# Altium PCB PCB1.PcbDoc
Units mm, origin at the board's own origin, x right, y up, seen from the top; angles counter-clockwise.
Board outline 24 x 24.06 mm, 2 copper layers (Top Layer, Bottom Layer); 36 components, 33 nets, 153 pads, 41 vias.
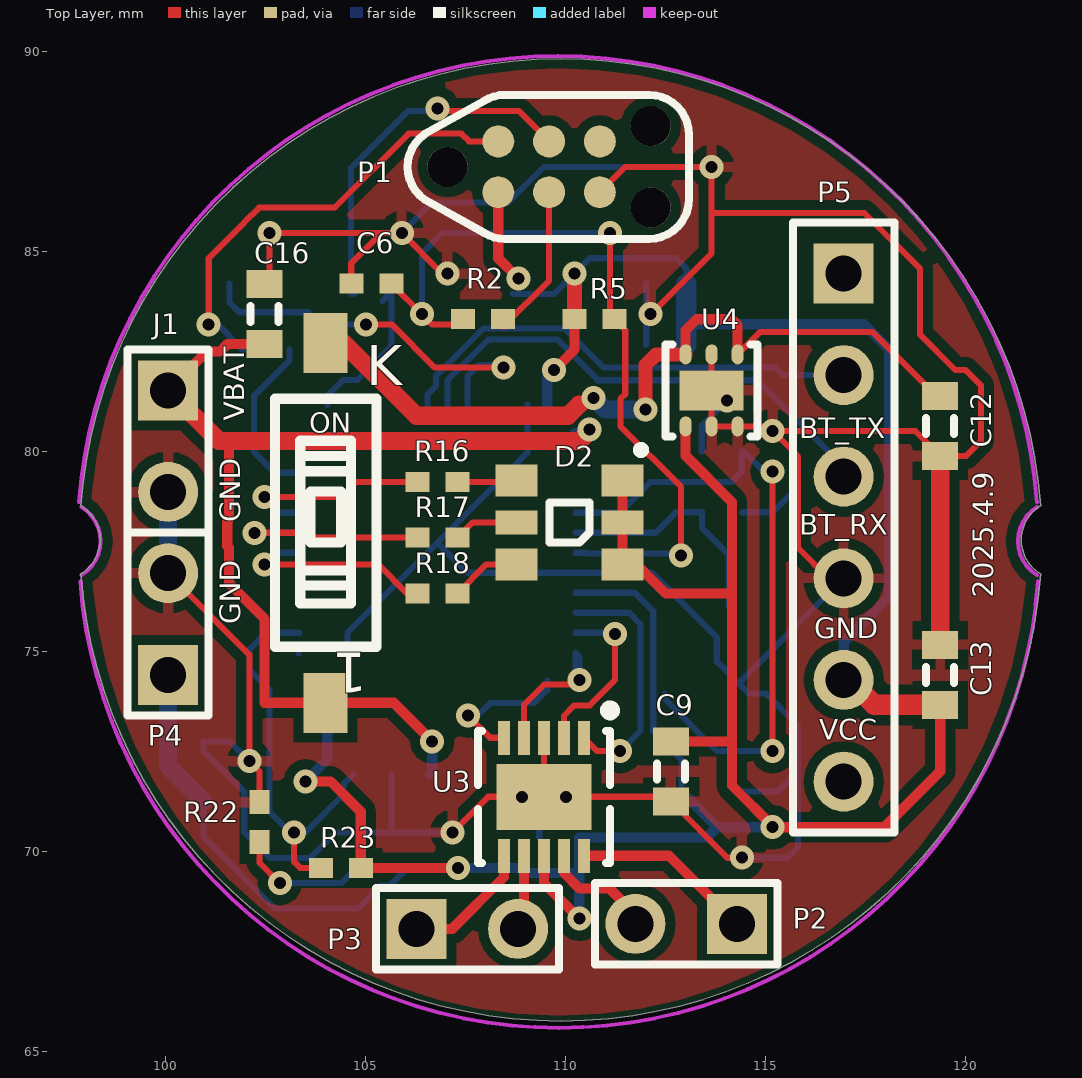
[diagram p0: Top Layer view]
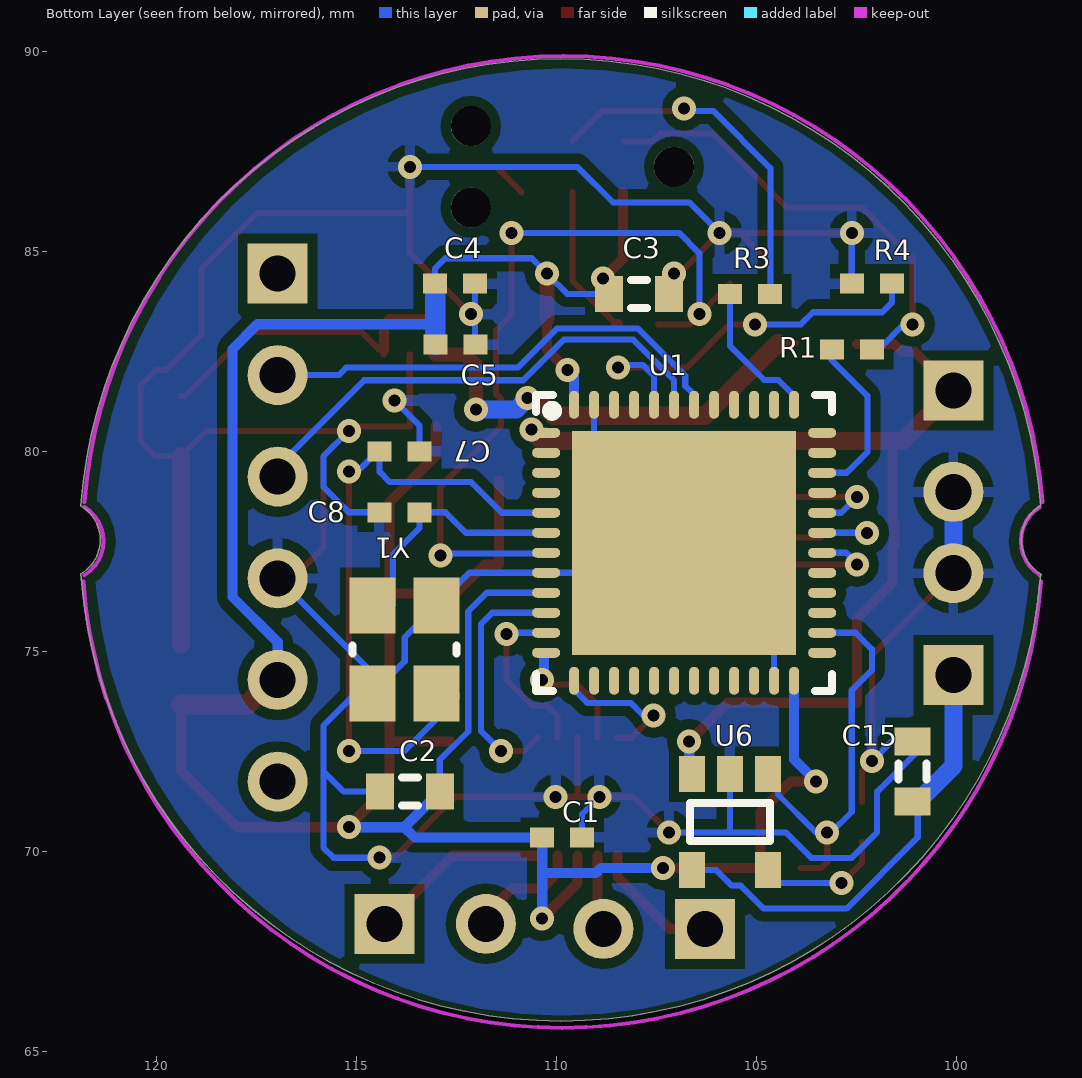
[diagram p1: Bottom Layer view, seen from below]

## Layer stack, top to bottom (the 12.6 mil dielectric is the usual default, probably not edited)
Top Solder: solder mask 0.0102, Solder Resist, Dk 3.5
Top Layer: signal copper 0.0356
Dielectric 1: dielectric 0.32, FR-4, Dk 4.8
Bottom Layer: signal copper 0.0356
Bottom Solder: solder mask 0.0102, Solder Resist, Dk 3.5

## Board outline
97.893,76.946 ccw(c97.392,77.796) 97.894,78.646 cw(c109.892,77.796) 121.89,78.648 121.891,78.646 ccw(c122.392,77.796) 121.89,76.946 cw(c109.892,77.796)

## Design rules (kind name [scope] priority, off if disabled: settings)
Clearance [All] p1: gap=0.254 except(0.127: Arc-Arc Track-SMDPad Arc-Track Arc-SMDPad Track-Track SMDPad-SMDPad)
PolygonConnect [All] p1: connectstyle=Relief reliefconductorwidth=0.254 reliefentries=4 polygonreliefangle="90 Angle" airgapwidth=0.254
RoutingVias [All] p1: holewidth=0.711 width=1.27 viastyle="Through Hole" minholewidth=0.711 minwidth=1.27 maxholewidth=0.711 maxwidth=1.27
SolderMaskExpansion [All] p1: expansion=0.102
UnpouredPolygon [All] p1: allowunpoured=FALSE
Width [All] p1: maxlimit=0.254 minlimit=0.127 preferedwidth=0.152 minimp=50.000000 maximp=50.000000 favimp=50.000000
29 further rules are at their usual default settings.

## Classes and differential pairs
net class MOTOR_CONTROL[1..4]: MOTOR_CONTROL1 MOTOR_CONTROL2 MOTOR_CONTROL3 MOTOR_CONTROL4
net class RGBLED[1..3]: RGBLED1 RGBLED2 RGBLED3

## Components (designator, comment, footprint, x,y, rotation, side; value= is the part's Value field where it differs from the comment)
C1 "10nF" 0402 109.855,70.358 r0 bottom
C2 "1uF" 0603 113.665,71.502 r180 bottom
C3 "4.7uF" 0603 107.938,83.947 r0 bottom
C4 "100nF" 0402 112.53,84.201 r0 bottom
C5 "100nF" 0402 112.522,82.677 r0 bottom
C6 "100nF" 0402 105.156,84.201 r0 top
C7 "22pF" 0402 113.919,80.01 r0 bottom
C8 "22pF" 0402 113.927,78.486 r180 bottom
C9 "10uF" 0603 112.649,72.009 r90 top
C12 "1uF" 0603 119.38,80.645 r90 top
C13 "1uF" 0603 119.38,74.422 r270 top
C15 "4.7uF" 0603 101.092,72.009 r270 bottom
C16 "4.7uF" 0603 102.489,83.439 r270 top
D2 "SMLVN6RGB1W1" "3.5x2.8 mm 6-SMD" 110.109,78.232 r180 top
J1 "78171-0002" HDR1*2 100.076,80.264 r0 top
K "2.54-1P-PGT" SW-SMD_2P-L6.2-LS9.4 104.013,78.359 r90 top
P1 "TC2030-IDC-NL" TC2030-IDC-NL 109.601,87.122 r0 top
P2 "HEADER 2X1 0.05\" UNPOLARIZED" HDR1*2 113.03,68.199 r270 top
P3 "HEADER 2X1 0.05\" UNPOLARIZED" HDR1*2 107.557,68.072 r90 top
P4 "CHARGING PAD" HDR1*2 100.076,75.692 r180 top
P5 "Header 6" HDR1X6 116.967,84.455 r270 top
R1 "22R" 0402 102.616,82.55 r180 bottom
R2 "22R" 0402 107.95,83.312 r0 top
R3 "22R" 0402 105.164,83.947 r180 bottom
R4 "100K" 0402 102.108,84.201 r180 bottom
R5 "100K" 0402 110.736,83.312 r180 top
R16 "22.6R" 0402 106.807,79.248 r0 top
R17 "130R" 0402 106.807,77.851 r0 top
R18 "24.9R" 0402 106.807,76.454 r0 top
R22 "10K" 0402 102.362,70.739 r90 top
R23 "100K" 0402 104.394,69.596 r0 top
U1 "STM32F051C8U6" QFN50P700X700X60_HS-49L 106.807,77.724 r180 bottom
U3 "A3901SEJTR-T" DFN50P300X300X75_HS-11N 109.474,71.374 r180 top
U4 "ADP122ACPZ-3.3-R7" "LFCSP-6 2.0X2.0X0.55" 113.665,81.534 r0 top
U6 "MCP73831T-2ACI/OT" SOT-23-OT5_L 105.664,70.739 r270 bottom
Y1 "7V-16.000MAAE-T" "3.2x2.5 CRYSTAL" 113.792,75.057 r90 bottom

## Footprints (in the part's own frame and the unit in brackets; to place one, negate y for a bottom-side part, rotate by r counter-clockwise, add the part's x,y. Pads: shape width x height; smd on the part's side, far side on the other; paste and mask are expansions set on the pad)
"3.2x2.5 CRYSTAL" [mm]
  rect 1.4x1.15 smd: 1(-1.1,-0.8) 2(1.1,-0.8) 3(1.1,0.8) 4(-1.1,0.8)
  silkscreen extent -0.1,-1.3 0.1,1.3, body extent -1.6,-1.25 1.6,1.25, height 0.8
"3.5x2.8 mm 6-SMD" [mm] "3.5 x 2.8 mm 6-SMD Flat Leads"
  rect 1.05x0.8 smd: 1(-1.325,1.05) 3(-1.325,-1.05) 4(1.325,-1.05) 6(1.325,1.05)
  rect 1.05x0.6 smd: 2(-1.325,0) 5(1.325,0)
  silkscreen extent -0.5,-0.5 0.5,0.5, body extent -1.75,-1.4 1.75,1.4, height 0.6
0402 [mm] "Chip Body 1.0 x 0.5 mm (LxW typ)"
  rect 0.6x0.5 smd: 1(-0.5,0) 2(0.5,0)
  body extent -0.55,-0.3 0.55,0.3, height 0.55
0603 [mm] "Chip Body 1.6 x 0.8 mm (LxW typ)"
  rect 0.7x0.9 smd: 1(-0.75,0) 2(0.75,0)
  silkscreen extent -0.2,-0.35 0.2,0.35, body extent -0.85,-0.48 0.85,0.48, height 0.9
DFN50P300X300X75_HS-11N [mm]
  rect 0.3x0.85 smd: 1(-1,-1.475) 2(-0.5,-1.475) 3(0,-1.475) 4(0.5,-1.475) 5(1,-1.475) 6(1,1.475) 7(0.5,1.475) 8(0,1.475) 9(-0.5,1.475) 10(-1,1.475)
  rect 2.38x1.65 smd: 11(0,0)
  silkscreen extent -1.78,-2.28 1.65,1.65, body extent -1.5,-1.5 1.5,1.5, height 0.75
HDR1*2 [mm]
  rect 1.5x1.5 hole 0.9: 1(0,1.27)
  round 1.5 hole 0.9: 2(0,-1.27)
  silkscreen extent -1.02,-2.29 1.02,2.29
HDR1X6 [mm] "Connector; Header; 6 Position"
  rect 1.5x1.5 hole 0.9: 1(0,0)
  round 1.5 hole 0.9: 2(2.54,0) 3(5.08,0) 4(7.62,0) 5(10.16,0) 6(12.7,0)
  silkscreen extent -1.27,-1.27 13.97,1.27
"LFCSP-6 2.0X2.0X0.55" [mm] ". 6-Lead Lead Frame Chip Scale Package [LFCSP_UD]  2.00 mm?2.00 mm Body, Ultra Thin, Dual Lead  (CP-6-3)"
  oval 0.3x0.5 smd: 1(-0.65,-0.9) 2(0,-0.9) 3(0.65,-0.9) 4(0.65,0.9) 5(0,0.9) 6(-0.65,0.9)
  rect 1.6x1 smd: 7(0,0)
  silkscreen extent -1.86,-1.59 1.15,1.15, body extent -1,-1 1,1, height 0.6
QFN50P700X700X60_HS-49L [mm] "QFN, 48-Leads, Body 7,00x7,00mm, Pitch 0,50mm, Thermal Pad 5,60x5,60mm, IPC High Density"
  oval 0.7x0.25 smd: 1(-3.45,2.75) 2(-3.45,2.25) 3(-3.45,1.75) 4(-3.45,1.25) 5(-3.45,0.75) 6(-3.45,0.25) 7(-3.45,-0.25) 8(-3.45,-0.75) 9(-3.45,-1.25) 10(-3.45,-1.75) 11(-3.45,-2.25) 12(-3.45,-2.75) 25(3.45,-2.75) 26(3.45,-2.25) 27(3.45,-1.75) 28(3.45,-1.25) 29(3.45,-0.75) 30(3.45,-0.25) 31(3.45,0.25) 32(3.45,0.75) 33(3.45,1.25) 34(3.45,1.75) 35(3.45,2.25) 36(3.45,2.75)
  oval 0.25x0.7 smd: 13(-2.75,-3.45) 14(-2.25,-3.45) 15(-1.75,-3.45) 16(-1.25,-3.45) 17(-0.75,-3.45) 18(-0.25,-3.45) 19(0.25,-3.45) 20(0.75,-3.45) 21(1.25,-3.45) 22(1.75,-3.45) 23(2.25,-3.45) 24(2.75,-3.45) 37(2.75,3.45) 38(2.25,3.45) 39(1.75,3.45) 40(1.25,3.45) 41(0.75,3.45) 42(0.25,3.45) 43(-0.25,3.45) 44(-0.75,3.45) 45(-1.25,3.45) 46(-1.75,3.45) 47(-2.25,3.45) 48(-2.75,3.45)
  rect 5.6x5.6 smd: 49(0,0)
  silkscreen extent -3.7,-3.7 3.7,3.7, body extent -3.55,-3.55 3.55,3.55, height 0.6
SOT-23-OT5_L [mm] "SOT23, 5-Leads, Body 2.9x1.6mm, Pitch 0.95mm, Lead Span 2.7mm, IPC High Density"
  rect 0.9x0.65 smd: 1(-1.2,0.95) 2(-1.2,0) 3(-1.2,-0.95) 4(1.2,-0.95) 5(1.2,0.95)
  silkscreen extent -0.48,-1 0.48,1, body extent -0.9,-1.55 0.9,1.55, height 1.45
SW-SMD_2P-L6.2-LS9.4 [mm]
  rect 1.5x1.1 smd paste+0 mask+0.051: 1(-4.636,-0.002) 2(4.364,-0.002)
  silkscreen extent -3.24,-1.27 2.96,1.27
TC2030-IDC-NL [mm] "TagConnector TC2030-IDC-NL"
  round 0.8 smd paste-1: 1(-1.27,-0.635) 2(-1.27,0.635) 3(0,-0.635) 4(0,0.635) 5(1.27,-0.635) 6(1.27,0.635)
  round 1 hole 1 unplated mask+0: ""(-2.54,0) ""(2.54,-1.016) ""(2.54,1.016)
  Top Layer pour cut-out: -1.27,-0.085 -1.27,0.085 -1.06,0.127 -0.881,0.246 -0.762,0.425 -0.72,0.635 -0.72,0.635 -0.55,0.635 -0.496,0.396 -0.343,0.205 -0.122,0.099 0.122,0.099 0.343,0.205 0.496,0.396 0.55,0.635 0.55,0.635 0.72,0.635 0.762,0.425 0.881,0.246 1.06,0.127 1.27,0.085 1.27,0.085 1.27,-0.085 1.06,-0.127 0.881,-0.246 0.762,-0.425 0.72,-0.635 0.72,-0.635 0.55,-0.635 0.496,-0.396 0.343,-0.205 0.122,-0.099 -0.122,-0.099 -0.343,-0.205 -0.496,-0.396 -0.55,-0.635 -0.55,-0.635 -0.72,-0.635 -0.762,-0.425 -0.881,-0.246 -1.06,-0.127 -1.27,-0.085
  silkscreen extent -3.54,-1.8 3.5,1.8, body extent -1.67,-1.03 1.67,1.03, height 0

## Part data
C1: "10nF 0402 X7R 25V ±5%"
C2 C12 C13: "1uF 0603 X5R 10V ±10%"
C3 C15 C16: "4.7uF 0603 X5R 10V ±10%"
C4 C5 C6: "100nF 0402 X7R 16V ±10%"
C7 C8: "22pF 0402 NP0/CG0 50V ±5%"
C9: "10uF 0603 X5R 6.3V ±20%"
D2: "ROHM SMLVN6RGB1W1 LED Tri-Color Blue/Green/Red Chip LED 6-Pin 1411 T/RLED Tri-Color Blue/Green/Red Chip LED 6-Pin 1411"
J1: "Molex Pico-EZmate? Wire-to-Board Header, 2 contacts"
P1: "TagConnect TC2030-IDC-NL SWD Programming Connector"
P5: "Header, 6-Pin"
R1 R2 R3: "22R 0402 1/16W ±1%"
R4 R5 R23: "100K 0402 1/16W ±1%"
R16: "22.6R 0402 1/16W ±0.05R"
R17: "130R 0402 1/16W ±0.05R"
R18: "24.9R 0402 1/16W ±0.05R"
R22: "10K 0402 1/16W ±1%"
U1: "STMICROELECTRONICS  STM32F051C8U6  MCU 32BIT CORTEX-M0 48MHZ UFQFPN-48"
U3: "ALLEGRO MICROSYSTEMS - A3901SEJTR-T - IC, MOTOR DRIVER"
U4: "Analog Devices ADP122ACPZ-3.3-R7 - 5.5 V Input, 300 mA, Low Quiescent  Current, CMOS Linear Regulator"
U6: "Miniature Single-Cell, Fully Integrated Li-Ion, Li-Polymer Charge Management Controller, 4.2V, 5-Pin SOT-23, Industrial Temperature, Tape and Reel"
Y1: "TXC - 7V-16.000MAAE-T, 16MHZ, 30PPM, 12PF - CRYSTAL"

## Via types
v1: diameter 0.6, hole 0.3, Top Layer to Bottom Layer, 41 vias

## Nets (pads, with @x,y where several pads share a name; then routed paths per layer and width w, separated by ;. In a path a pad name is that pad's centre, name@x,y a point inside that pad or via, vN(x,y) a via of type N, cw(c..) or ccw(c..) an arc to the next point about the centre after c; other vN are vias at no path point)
+3.3V: C1.2 C2.2 C3.2 C4.2 C5.2 C9.2 C13.2 D2.1 D2.2 D2.3 P1.1 P5.5 R5.2 R23.2 U1.9 U1.24 U1.48 U3.8 U4.1 | length 81.6
  Top Layer w0.152: P5.5 P5.5@117.105,74.295
  Top Layer w0.254: v1(103.513,71.756) 104.139,71.756 104.894,71.001 R23.2 v1(107.33,69.597) ; P1.1 108.331,84.836 v1(108.838,84.329) ; U3.8 109.474,69.215 v1(110.363,68.326) ; v1(109.727,82.043) 110.236,82.552 R5.2 ; D2.3 D2.2 D2.1 111.794,77.182 112.522,76.454 114.173,76.454 ; C9.2 114.161,72.759 114.173,72.771 ; U4.1 113.015,79.898 114.173,78.74 114.173,76.454 ; v1(115.188,70.613) v1@115.214,70.613 ; C13.2 119.38,72.009 117.984,70.613 v1@115.214,70.613 ; 114.173,72.771 114.173,76.454 ; 114.173,72.771 114.173,71.654 v1@115.214,70.613
  Top Layer w0.381: R5.2 v1(110.236,84.455)
  Top Layer w0.508: P5.5@117.105,74.295 117.728,73.672 C13.2
  Bottom Layer w0.152: C3.2 109.728,83.947 v1(110.236,84.455) 110.617,84.836 112.776,84.836 113.03,84.582 C4.2 ; U1.9 111.74,76.474 112.205,76.009 112.205,73.006 112.915,72.295 C2.2@112.915,71.601
  Bottom Layer w0.254: v1@103.505,71.755 104.057,72.307 U1.24 ; v1(107.33,69.597) 108.802,69.597 108.803,69.596 108.883,69.596 109.007,69.472 110.355,69.472 ; U1.48 109.557,81.871 v1@109.601,81.915 ; v1@110.355,68.334 110.355,69.472 ; C2.2 113.803,70.613 ; 113.03,83.185 117.475,83.185 118.098,82.562 118.098,76.367 116.967,75.236 P5.5 ; v1(115.188,70.613) 113.803,70.613 ; 110.355,69.472 C1.2 113.548,70.358 113.803,70.613
  Bottom Layer w0.508: C5.2@113.03,82.677 113.03,83.185 C4.2
BT_RX: P5.3 U1.43 | length 12.5
  Bottom Layer w0.152: U1.43 107.057,81.784 108.077,82.804 109.813,82.804 110.829,81.788 114.808,81.788 116.967,79.629 P5.3
BT_TX: P5.2 U1.42 | length 12
  Bottom Layer w0.152: U1.42 106.557,81.425 106.778,81.646 106.778,81.9 107.961,83.083 109.982,83.083 110.964,82.102 115.256,82.102 115.443,81.915 P5.2
CHARGING: R23.1 U1.26 U6.1 | length 10.2
  Top Layer w0.152: v1(103.229,70.486) 103.229,69.747 103.38,69.596 R23.1
  Bottom Layer w0.152: U1.26 102.523,75.474 102.113,75.064 102.113,74.542 102.482,74.173 102.484,74.173 102.616,74.041 102.616,70.993 103.124,70.485 103.514,70.485 104.46,71.431 104.46,71.685 U6.1
GND: C1.1 C2.1 C3.1 C4.1 C5.1 C6.1 C7.1 C8.1 C9.1 C12.1 C13.1 C15.1 C16.1 J1.2 P1.5 P4.2 P5.4 R4.1 R22.2 U1.8 U1.23 U1.47 U1.49 U3.3 U3.11 U4.2 U4.3 U4.5 U4.7 U6.2 Y1.2 Y1.4 | length 121.3
  Top Layer w0.152: P4.2@100.076,76.581 100.457,76.581 102.108,74.93 v1(102.108,72.263) 102.362,72.009 R22.2 ; C16.1 102.616,84.316 v1(102.616,85.471) 105.418,85.471 ; C6.1 104.656,84.709 105.418,85.471 ; v1(107.061,84.455) 106.934,84.455 v1(105.918,85.471) 105.418,85.471 ; v1(107.188,70.485) 108.077,71.374 v1(108.924,71.374) U3.11 ; U3.3 U3.11 ; P1.5 111.506,87.122 v1(113.665,87.122) 113.665,85.979 ; v1(112.141,83.439) 113.665,84.963 113.665,85.979 ; U4.5 U4.7 U4.2 U4.3 115.073,80.634 v1(115.189,80.518) ; v1(114.419,69.85) 114.058,69.85 C9.1 112.534,71.374 v1(110.024,71.374) U3.11 ; P5.4 116.586,76.835 115.824,77.597 115.824,79.883 v1(115.189,80.518) ; 113.665,85.979 113.677,85.967 117.487,85.967 118.872,84.582 118.872,82.932 119.762,82.042 120.015,82.042 120.396,81.661 120.396,80.264 120.027,79.895 C12.1 118.757,80.518 v1(115.189,80.518)
  Top Layer w0.452: C13.1 C12.1
  Bottom Layer w0.152: C15.1@100.965,72.759 100.965,72.517 101.981,71.501 101.981,70.485 102.62,69.846 103.628,69.846 104.267,70.485 105.728,70.485 ; C15.1 101.612,72.759 v1(102.108,72.263) ; R4.1@102.616,84.209 v1(102.616,85.471) ; U1.23 104.557,75.474 U1.49 ; U6.2 105.664,70.549 105.728,70.485 ; v1(105.918,85.471) 106.68,86.233 108.585,86.233 109.474,87.122 v1(113.665,87.122) ; v1(107.188,70.485) 105.728,70.485 ; v1(108.924,71.374) 109.355,70.943 C1.1 ; U1.47 109.057,79.974 U1.49 ; C5.1@112.03,82.677 C4.1 ; C7.1 113.419,80.653 v1(114.046,81.28) ; C2.1 115.316,71.501 115.824,72.009 ; v1(114.419,69.85) 115.57,69.85 115.824,70.104 115.824,72.009 ; C8.1 115.189,78.486 115.824,79.121 115.824,79.883 v1(115.189,80.518) ; P5.4 116.962,76.835 Y1.4@114.338,74.211 ; U1.49 107.557,76.974 U1.8 112.175,76.974 Y1.2 113.792,75.357 113.792,74.757 Y1.4@114.338,74.211 ; Y1.4@114.338,74.211 Y1.4 115.019,73.957 115.824,73.152 115.824,72.009
  Bottom Layer w0.452: P4.2@100.076,76.581 J1.2
IMU_INT: U1.25 | length 0
  Bottom Layer w0.152: U1.25@103.338,74.955 U1.25@103.342,74.959
MCU_X1_16MHZ: C7.2 U1.5 Y1.1 | length 16.4
  Top Layer w0.152: v1(115.189,72.517) v1(115.189,79.502)
  Bottom Layer w0.152: U1.5 111.367,78.474 112.141,79.248 114.173,79.248 114.419,79.494 C7.2 114.469,80.01 114.891,79.588 115.103,79.588 v1(115.189,79.502) ; Y1.1@112.484,73.957 112.484,73.832 113.799,72.517 v1(115.189,72.517)
MCU_X2_16MHZ: C8.2 U1.6 Y1.3 | length 6
  Bottom Layer w0.152: U1.6 112.264,77.974 112.776,78.486 C8.2 113.427,78.089 114.084,77.432 Y1.3@114.084,76.157
MOTOR_CONTROL1: U1.10 U3.1 | length 6.2
  Top Layer w0.152: U3.1 110.806,72.517 v1(111.379,72.517)
  Bottom Layer w0.152: U1.10 111.605,75.974 111.887,75.692 111.887,73.025 v1(111.379,72.517)
MOTOR_CONTROL2: U1.11 U3.2 | length 4.4
  Top Layer w0.152: U3.2 109.974,73.398 110.236,73.66 110.617,73.66 111.252,74.295 v1(111.252,75.438)
  Bottom Layer w0.152: U1.11 111.216,75.474 v1(111.252,75.438)
MOTOR_CONTROL3: U1.12 U3.4 | length 3.9
  Top Layer w0.152: U3.4 108.974,73.676 109.474,74.176 110.244,74.176 v1(110.363,74.295)
  Bottom Layer w0.152: v1@110.257,74.295 U1.12 110.363,74.868 v1(110.363,74.295)
MOTOR_CONTROL4: U1.13 U3.5 | length 3.6
  Top Layer w0.152: v1(107.569,73.406) 108.126,72.849 U3.5
  Bottom Layer w0.152: v1(107.569,73.406) 107.823,73.406 108.138,73.721 109.229,73.721 109.557,74.049 U1.13
NetC12_2: C12.2 K.2 U4.4 U4.6 | length 19.9
  Top Layer w0.152: K.2 K.2@104.463,82.723 ; 110.356,81.18 110.644,81.18 v1@110.744,81.28 ; U4.6 U4.6@113.015,82.471 ; U4.4 U4.4@114.315,82.534 ; U4.4@114.383,82.562 114.443,82.562 114.876,82.995 117.68,82.995 119.28,81.395 C12.2
  Top Layer w0.252: U4.6@113.015,82.471 113.015,83.043 113.284,83.312 114.173,83.312 114.315,83.17 U4.4@114.315,82.534
  Top Layer w0.354: v1(112.014,81.058) 112.014,82.169 112.279,82.434 U4.6
  Top Layer w0.452: K.2@104.463,82.723 106.287,80.899 110.075,80.899 110.356,81.18
  Bottom Layer w0.152: v1@110.744,81.28 110.844,81.18 v1@110.878,81.18
  Bottom Layer w0.452: v1@110.878,81.18 111,81.058 v1(112.014,81.058)
  other v1: 110.717,81.339
NetC15_2: C15.2 P4.1 U6.4 | length 11.2
  Bottom Layer w0.152: C15.2@100.965,71.259 100.965,70.358 102.743,68.58 104.817,68.58 105.39,69.152 105.613,69.152 106,69.539 U6.4
  Bottom Layer w0.452: P4.1 100.076,72.148 C15.2@100.965,71.259
NetD2_4: D2.4 R16.2 | length 1.5
  Top Layer w0.152: R16.2 108.75,79.248 D2.4
NetD2_5: D2.5 R17.2 | length 1.6
  Top Layer w0.152: R17.2 107.315,77.851 107.696,78.232 D2.5
NetD2_6: D2.6 R18.2 | length 1.8
  Top Layer w0.152: R18.2 108.035,77.182 D2.6
NetP1_2: P1.2 R1.2 | length 11.4
  Top Layer w0.152: v1(101.092,83.185) 101.092,84.836 101.986,85.73 101.986,85.732 102.355,86.101 102.357,86.101 102.362,86.106 104.244,86.106 106.09,87.952 107.405,87.952 107.6,87.757 P1.2
  Bottom Layer w0.152: v1(101.092,83.185) 101.313,83.185 R1.2@101.948,82.55
NetP1_3: P1.3 R2.2 | length 3.8
  Top Layer w0.152: R2.2@108.508,83.185 109.601,84.278 P1.3
  Top Layer w0.254: R2.2@108.458,83.185 R2.2@108.508,83.185
NetP1_4: P1.4 R3.2 | length 9.4
  Top Layer w0.152: v1(106.807,88.582) 106.87,88.519 108.839,88.519 P1.4
  Bottom Layer w0.152: R3.2@104.888,84.121 104.714,83.947 R3.2 104.648,83.963 104.648,87.09 106.077,88.519 106.744,88.519 v1(106.807,88.582)
NetP2_1: P2.1 U3.10 | length 4.5
  Top Layer w0.252: U3.10 112.6,69.899 P2.1
NetP2_2: P2.2 U3.9 | length 2.9
  Top Layer w0.252: U3.9 109.974,69.466 110.363,69.077 111.12,69.077 111.76,68.437 P2.2
NetP3_1: P3.1 U3.6 | length 3.3
  Top Layer w0.252: P3.1 107.18,68.072 108.474,69.366 U3.6
NetP3_2: P3.2 U3.7 | length 1.9
  Top Layer w0.152: P3.2 P3.2@108.974,68.219
  Top Layer w0.252: P3.2@108.974,68.219 U3.7
NetR4_2: R4.2 U1.44 | length 9.8
  Top Layer w0.152: v1(105.029,83.185) 105.664,83.185 106.747,82.102 v1(108.458,82.102)
  Bottom Layer w0.152: R4.2 101.608,83.732 101.854,83.486 103.585,83.486 103.886,83.185 v1(105.029,83.185) ; U1.44 107.557,81.889 107.837,82.169 108.391,82.169 v1(108.458,82.102)
NetR22_1: R22.1 U6.5 | length 3.6
  Top Layer w0.152: R22.1 102.362,69.723 v1(102.869,69.216) v1@102.997,69.088
  Bottom Layer w0.152: v1@102.997,69.088 v1(102.869,69.216) 104.409,69.216 U6.5@104.723,69.53
NRST: C6.2 R2.1 R5.1 U1.7 | length 20.1
  Top Layer w0.152: C6.2 106.426,83.431 106.672,83.185 R2.1@107.458,83.185 ; v1(111.124,85.472) 111.124,83.424 R5.1 111.506,83.042 111.506,81.441 111.384,81.319 111.384,80.64 112.903,79.121 v1(112.903,77.411)
  Bottom Layer w0.152: v1(106.426,83.439) 106.426,84.961 106.425,84.962 106.934,85.471 v1@110.998,85.471 ; U1.7 110.508,77.474 110.527,77.455 112.859,77.455 v1(112.903,77.411)
RGBLED1: R17.1 U1.31 | length 5
  Top Layer w0.152: v1(102.235,77.974) 103.282,77.974 103.405,77.851 R17.1@106.053,77.851
  Bottom Layer w0.152: v1(102.235,77.974) U1.31
RGBLED2: R16.1 U1.32 | length 4.8
  Top Layer w0.152: v1(102.489,78.867) 104.394,78.867 104.775,79.248 R16.1@106.053,79.248
  Bottom Layer w0.152: v1(102.489,78.867) 102.882,78.474 U1.32
RGBLED3: R18.1 U1.30 | length 4.7
  Top Layer w0.152: v1(102.489,77.182) 105.325,77.182 R18.1@106.053,76.454
  Bottom Layer w0.152: v1@102.624,77.343 102.755,77.474 U1.30
SWCLK: R3.1 U1.37 | length 3.9
  Bottom Layer w0.152: U1.37 104.057,81.399 104.451,81.793 104.808,81.793 105.664,82.649 R3.1 105.614,83.947 R3.1@105.44,83.773
SWDIO: R1.1 U1.34 | length 4.3
  Bottom Layer w0.152: R1.1 103.116,82.288 102.227,81.399 102.227,79.99 102.743,79.474 U1.34
VBAT: C16.2 J1.1 K.1 U1.1 U6.3 | length 26.8
  Top Layer w0.254: J1.1 101.046,82.504 101.374,82.504 101.559,82.689 C16.2 ; 101.6,80.264 101.6,78.302 101.554,78.256 101.554,77.646 101.6,77.6 101.6,76.708 102.489,75.819 102.489,73.723 K.1 105.716,73.723 v1(106.68,72.759)
  Top Layer w0.454: J1.1 101.346,80.264 101.6,80.264 110.363,80.264 v1@110.617,80.518
  Bottom Layer w0.254: U6.3 106.68,72.005 v1(106.68,72.759) ; U1.1 110.541,80.474 v1(110.617,80.55)
pads on no net: P1. P1.6 P5.1 P5.6 U1.2 U1.3 U1.4 U1.14 U1.15 U1.16 U1.17 U1.18 U1.19 U1.20 U1.21 U1.22 U1.27 U1.28 U1.29 U1.33 U1.35 U1.36 U1.38 U1.39 U1.40 U1.41 U1.45 U1.46

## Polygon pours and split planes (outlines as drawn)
GND on Bottom Layer "Bottom Layer-No Net" (solid, remove dead copper, pour order 4): 97.79,90.17 121.92,90.17 121.92,65.659 121.793,65.532 97.79,65.532 97.79,90.17
GND on Top Layer "Bottom Layer-No Net" (solid, remove dead copper, pour order 6): 97.79,90.17 121.92,90.17 121.92,65.405 97.79,65.405 97.79,90.17

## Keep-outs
Keep-Out Layer:
  lines w0.1: 97.853,78.74 cw(c109.823,77.892) 121.793,78.74 ; 97.885,76.749 ccw(c109.855,77.597) 121.825,76.749 ; 97.917,76.917 ccw(c97.387,77.765) 97.917,78.613 ; 121.793,76.917 cw(c122.323,77.765) 121.793,78.613

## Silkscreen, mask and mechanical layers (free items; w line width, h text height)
Top Overlay:
  text "VBAT" at 101.981,80.772 h0.51 r90
  text "BT_TX" at 115.849,80.332 h0.51
  text "GND" at 101.884,78.232 h0.51 r90
  text "BT_RX" at 115.849,77.919 h0.51
  text "2025.4.9" at 120.709,76.352 h0.51 r90
  text "GND" at 101.884,75.692 h0.51 r90
  text "GND" at 116.23,75.336 h0.51
  text "VCC" at 116.357,72.796 h0.51
Mechanical 2:
  lines w0.254: 97.893,76.946 ccw(c97.392,77.796) 97.894,78.646 cw(c109.892,77.796) 121.89,78.648 ; 97.894,76.944 ccw(c109.892,77.796) 121.89,76.946 cw(c122.392,77.796) 121.891,78.646
Mechanical 10:
  lines w0.1: 97.885,78.699 cw(c109.855,77.851) 121.825,78.699 ; 97.855,76.943 ccw(c109.825,77.791) 121.795,76.943 ; 97.855,76.943 ccw(c97.325,77.791) 97.855,78.639 ; 97.855,76.943 ccw(c97.325,77.791) 97.855,78.639 ; 97.855,76.943 ccw(c109.825,77.791) 121.795,76.943 ; 97.855,78.639 cw(c109.825,77.791) 121.795,78.639 ; 97.855,78.639 cw(c109.825,77.791) 121.795,78.639 ; 97.982,76.943 ccw(c97.452,77.791) 97.982,78.639 ; 97.982,76.943 ccw(c109.952,77.791) 121.922,76.943 ; 97.982,76.943 ccw(c109.952,77.791) 121.922,76.943 ; 97.982,76.943 ccw(c97.452,77.791) 97.982,78.639 ; 97.982,78.639 cw(c109.952,77.791) 121.922,78.639 ; 97.982,78.639 cw(c109.952,77.791) 121.922,78.639 ; 121.795,76.943 cw(c122.325,77.791) 121.795,78.639 ; 121.795,76.943 cw(c122.325,77.791) 121.795,78.639 ; 121.922,76.943 cw(c122.452,77.791) 121.922,78.639 ; 121.922,76.943 cw(c122.452,77.791) 121.922,78.639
